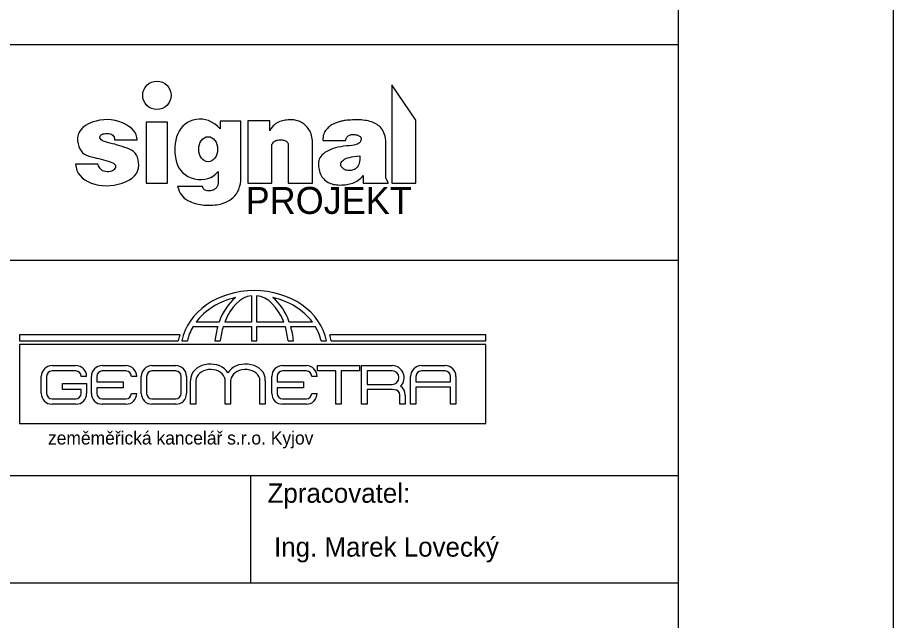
# Model space of a CAD drawing. Extents: x 2583 to 4283, y -3016 to -2572.
# Drawn here: x 3456.4 to 3537.7, y -2917.2 to -2861.3 of the extents above; entities that cross this region are included whole.
import ezdxf

# ---------------------------------------------------------------- set-up
doc = ezdxf.new("R2010")
doc.units = 0
for name, color, linetype in [('Default', 7, 'Continuous'), ('Vrstva 1', 7, 'Continuous'), ('Vrstva 11', 7, 'Continuous'), ('Vrstva 17', 7, 'Continuous'), ('Vrstva 6', 7, 'Continuous')]:
    doc.layers.add(name, color=color, linetype=linetype)

msp = doc.modelspace()

# ---------------------------------------------------------------- linework, layer by layer
at = {"layer": 'Default'}
msp.add_lwpolyline([(3327.684, -3015.765), (3537.684, -3015.765), (3537.684, -2718.765), (3327.684, -2718.765)], close=True, dxfattribs=at)
at = {"layer": 'Vrstva 1'}
msp.add_lwpolyline([(3347.684, -2738.765), (3517.684, -2738.765), (3517.684, -2998.765), (3347.684, -2998.765)], close=True, dxfattribs=at)
at = {"layer": 'Vrstva 11'}
for points in [[(3493.348, -2876.644), (3493.348, -2870.804), (3491.108, -2867.524), (3491.108, -2876.644), (3493.348, -2876.644)], [(3464.62, -2876.879), (3464.982, -2876.862), (3465.348, -2876.814), (3465.719, -2876.735), (3466.095, -2876.625), (3466.45, -2876.489), (3466.758, -2876.333), (3467.019, -2876.157), (3467.233, -2875.961), (3467.4, -2875.745), (3467.521, -2875.509), (3467.594, -2875.253), (3467.621, -2874.977), (3467.61, -2874.704), (3467.572, -2874.455), (3467.506, -2874.231), (3467.412, -2874.031), (3467.291, -2873.856), (3467.141, -2873.706), (3466.964, -2873.581), (3466.76, -2873.48), (3466.54, -2873.394), (3466.318, -2873.312), (3466.094, -2873.235), (3465.868, -2873.162), (3465.639, -2873.094), (3465.408, -2873.029), (3465.174, -2872.97), (3464.939, -2872.914), (3464.717, -2872.859), (3464.526, -2872.8), (3464.365, -2872.737), (3464.235, -2872.67), (3464.135, -2872.599), (3464.065, -2872.524), (3464.026, -2872.445), (3464.018, -2872.362), (3464.034, -2872.282), (3464.071, -2872.213), (3464.127, -2872.155), (3464.203, -2872.108), (3464.299, -2872.072), (3464.414, -2872.046), (3464.55, -2872.032), (3464.705, -2872.028), (3464.86, -2872.039), (3464.996, -2872.068), (3465.111, -2872.115), (3465.205, -2872.181), (3465.28, -2872.265), (3465.335, -2872.367), (3465.369, -2872.487), (3465.384, -2872.626), (3467.463, -2872.626), (3467.444, -2872.384), (3467.381, -2872.155), (3467.276, -2871.937), (3467.128, -2871.733), (3466.938, -2871.542), (3466.704, -2871.363), (3466.427, -2871.197), (3466.108, -2871.043), (3465.766, -2870.914), (3465.421, -2870.819), (3465.073, -2870.76), (3464.723, -2870.735), (3464.37, -2870.745), (3464.014, -2870.79), (3463.656, -2870.869), (3463.295, -2870.984), (3462.957, -2871.126), (3462.668, -2871.289), (3462.427, -2871.472), (3462.235, -2871.676), (3462.091, -2871.901), (3461.997, -2872.145), (3461.95, -2872.411), (3461.953, -2872.697), (3461.992, -2872.978), (3462.058, -2873.23), (3462.151, -2873.453), (3462.269, -2873.645), (3462.414, -2873.809), (3462.585, -2873.943), (3462.782, -2874.047), (3463.005, -2874.122), (3463.24, -2874.182), (3463.471, -2874.241), (3463.699, -2874.3), (3463.923, -2874.359), (3464.143, -2874.418), (3464.36, -2874.476), (3464.573, -2874.534), (3464.783, -2874.592), (3464.975, -2874.652), (3465.136, -2874.716), (3465.267, -2874.785), (3465.366, -2874.859), (3465.435, -2874.937), (3465.473, -2875.019), (3465.48, -2875.106), (3465.456, -2875.197), (3465.409, -2875.285), (3465.348, -2875.362), (3465.273, -2875.426), (3465.183, -2875.479), (3465.079, -2875.521), (3464.96, -2875.551), (3464.827, -2875.569), (3464.68, -2875.576), (3464.532, -2875.566), (3464.396, -2875.532), (3464.272, -2875.477), (3464.161, -2875.398), (3464.062, -2875.297), (3463.976, -2875.173), (3463.902, -2875.027), (3463.84, -2874.858), (3461.76, -2874.858), (3461.804, -2875.165), (3461.887, -2875.447), (3462.01, -2875.705), (3462.173, -2875.939), (3462.375, -2876.148), (3462.617, -2876.333), (3462.898, -2876.494), (3463.219, -2876.631), (3463.562, -2876.74), (3463.91, -2876.817), (3464.263, -2876.864), (3464.62, -2876.879)], [(3470.308, -2876.644), (3470.308, -2870.964), (3468.308, -2870.964), (3468.308, -2876.644), (3470.308, -2876.644)], [(3474.168, -2878.686), (3474.336, -2878.682), (3474.506, -2878.674), (3474.678, -2878.66), (3474.852, -2878.642), (3475.026, -2878.615), (3475.2, -2878.576), (3475.374, -2878.525), (3475.547, -2878.462), (3475.72, -2878.386), (3475.893, -2878.298), (3476.066, -2878.199), (3476.238, -2878.087), (3476.402, -2877.957), (3476.551, -2877.804), (3476.683, -2877.629), (3476.8, -2877.43), (3476.901, -2877.208), (3476.986, -2876.963), (3477.055, -2876.695), (3477.108, -2876.404), (3477.108, -2870.884), (3475.188, -2870.884), (3475.188, -2871.604), (3474.922, -2871.349), (3474.652, -2871.136), (3474.377, -2870.964), (3474.098, -2870.833), (3473.815, -2870.743), (3473.528, -2870.694), (3473.236, -2870.687), (3472.94, -2870.72), (3472.653, -2870.788), (3472.388, -2870.885), (3472.144, -2871.011), (3471.922, -2871.164), (3471.722, -2871.347), (3471.544, -2871.558), (3471.388, -2871.797), (3471.253, -2872.065), (3471.142, -2872.351), (3471.057, -2872.644), (3470.998, -2872.944), (3470.965, -2873.251), (3470.958, -2873.566), (3470.977, -2873.888), (3471.022, -2874.216), (3471.093, -2874.553), (3471.193, -2874.876), (3471.325, -2875.167), (3471.491, -2875.425), (3471.689, -2875.65), (3471.92, -2875.843), (3472.183, -2876.003), (3472.479, -2876.13), (3472.808, -2876.225), (3473.144, -2876.283), (3473.463, -2876.3), (3473.763, -2876.277), (3474.046, -2876.213), (3474.312, -2876.108), (3474.559, -2875.963), (3474.789, -2875.776), (3475, -2875.55), (3475, -2876.626), (3474.982, -2876.714), (3474.959, -2876.796), (3474.931, -2876.871), (3474.899, -2876.942), (3474.863, -2877.006), (3474.822, -2877.065), (3474.776, -2877.118), (3474.726, -2877.165), (3474.67, -2877.207), (3474.608, -2877.243), (3474.538, -2877.274), (3474.461, -2877.3), (3474.377, -2877.32), (3474.286, -2877.335), (3474.188, -2877.344), (3474.083, -2877.348), (3473.979, -2877.343), (3473.886, -2877.324), (3473.802, -2877.292), (3473.729, -2877.247), (3473.666, -2877.189), (3473.614, -2877.117), (3473.571, -2877.032), (3473.539, -2876.934), (3471.232, -2876.934), (3471.301, -2877.162), (3471.384, -2877.371), (3471.481, -2877.561), (3471.592, -2877.732), (3471.717, -2877.885), (3471.855, -2878.019), (3472.008, -2878.134), (3472.174, -2878.23), (3472.346, -2878.313), (3472.517, -2878.387), (3472.686, -2878.453), (3472.854, -2878.51), (3473.02, -2878.558), (3473.185, -2878.598), (3473.348, -2878.629), (3473.51, -2878.652), (3473.672, -2878.668), (3473.835, -2878.679), (3474.001, -2878.685), (3474.168, -2878.686)], [(3483.748, -2876.644), (3483.748, -2872.844), (3483.745, -2872.674), (3483.731, -2872.511), (3483.706, -2872.354), (3483.671, -2872.204), (3483.625, -2872.06), (3483.568, -2871.924), (3483.5, -2871.793), (3483.421, -2871.67), (3483.336, -2871.553), (3483.249, -2871.445), (3483.16, -2871.345), (3483.069, -2871.254), (3482.976, -2871.17), (3482.881, -2871.095), (3482.784, -2871.028), (3482.685, -2870.969), (3482.583, -2870.918), (3482.477, -2870.873), (3482.366, -2870.836), (3482.251, -2870.806), (3482.131, -2870.782), (3482.008, -2870.765), (3481.88, -2870.756), (3481.748, -2870.753), (3481.614, -2870.756), (3481.481, -2870.764), (3481.35, -2870.777), (3481.22, -2870.795), (3481.091, -2870.818), (3480.963, -2870.846), (3480.836, -2870.879), (3480.711, -2870.917), (3480.587, -2870.965), (3480.466, -2871.03), (3480.347, -2871.111), (3480.231, -2871.209), (3480.116, -2871.323), (3480.005, -2871.453), (3479.895, -2871.6), (3479.788, -2871.764), (3479.788, -2870.844), (3477.748, -2870.844), (3477.748, -2876.644), (3479.988, -2876.644), (3479.988, -2873.084), (3480.023, -2872.993), (3480.067, -2872.912), (3480.121, -2872.841), (3480.186, -2872.78), (3480.26, -2872.729), (3480.344, -2872.688), (3480.438, -2872.657), (3480.542, -2872.636), (3480.648, -2872.623), (3480.749, -2872.616), (3480.844, -2872.615), (3480.934, -2872.62), (3481.019, -2872.632), (3481.099, -2872.649), (3481.173, -2872.673), (3481.242, -2872.703), (3481.305, -2872.737), (3481.359, -2872.776), (3481.404, -2872.818), (3481.442, -2872.864), (3481.471, -2872.913), (3481.492, -2872.966), (3481.504, -2873.023), (3481.508, -2873.084), (3481.508, -2876.644), (3483.748, -2876.644)], [(3486.311, -2876.808), (3486.473, -2876.805), (3486.63, -2876.796), (3486.784, -2876.782), (3486.933, -2876.762), (3487.077, -2876.736), (3487.217, -2876.705), (3487.353, -2876.667), (3487.485, -2876.624), (3487.614, -2876.573), (3487.741, -2876.511), (3487.866, -2876.44), (3487.99, -2876.357), (3488.112, -2876.264), (3488.232, -2876.161), (3488.351, -2876.048), (3488.468, -2875.924), (3488.468, -2876.644), (3490.788, -2876.644), (3490.788, -2876.564), (3490.548, -2876.164), (3490.548, -2872.684), (3490.522, -2872.479), (3490.486, -2872.289), (3490.441, -2872.113), (3490.386, -2871.952), (3490.321, -2871.805), (3490.247, -2871.673), (3490.164, -2871.555), (3490.071, -2871.452), (3489.97, -2871.359), (3489.862, -2871.273), (3489.749, -2871.195), (3489.629, -2871.123), (3489.503, -2871.058), (3489.37, -2871), (3489.232, -2870.948), (3489.087, -2870.904), (3488.935, -2870.866), (3488.776, -2870.834), (3488.609, -2870.808), (3488.436, -2870.787), (3488.255, -2870.772), (3488.067, -2870.763), (3487.872, -2870.759), (3487.67, -2870.761), (3487.471, -2870.767), (3487.287, -2870.775), (3487.118, -2870.786), (3486.963, -2870.799), (3486.823, -2870.814), (3486.698, -2870.831), (3486.588, -2870.85), (3486.492, -2870.872), (3486.404, -2870.896), (3486.314, -2870.921), (3486.224, -2870.949), (3486.134, -2870.978), (3486.042, -2871.01), (3485.95, -2871.043), (3485.857, -2871.079), (3485.764, -2871.116), (3485.671, -2871.158), (3485.578, -2871.206), (3485.487, -2871.262), (3485.397, -2871.324), (3485.308, -2871.393), (3485.22, -2871.469), (3485.132, -2871.551), (3485.046, -2871.641), (3484.966, -2871.738), (3484.897, -2871.845), (3484.838, -2871.962), (3484.791, -2872.087), (3484.754, -2872.222), (3484.728, -2872.367), (3484.713, -2872.521), (3484.708, -2872.684), (3486.828, -2872.684), (3486.844, -2872.587), (3486.868, -2872.5), (3486.901, -2872.422), (3486.942, -2872.353), (3486.992, -2872.294), (3487.051, -2872.243), (3487.118, -2872.202), (3487.194, -2872.169), (3487.275, -2872.145), (3487.356, -2872.127), (3487.437, -2872.116), (3487.519, -2872.111), (3487.602, -2872.113), (3487.685, -2872.121), (3487.769, -2872.136), (3487.853, -2872.157), (3487.933, -2872.183), (3488.005, -2872.211), (3488.067, -2872.24), (3488.121, -2872.272), (3488.166, -2872.307), (3488.203, -2872.343), (3488.23, -2872.381), (3488.249, -2872.422), (3488.26, -2872.465), (3488.265, -2872.511), (3488.264, -2872.559), (3488.257, -2872.611), (3488.243, -2872.665), (3488.223, -2872.722), (3488.197, -2872.782), (3488.165, -2872.844), (3488.114, -2872.905), (3488.033, -2872.961), (3487.921, -2873.012), (3487.78, -2873.057), (3487.608, -2873.097), (3487.405, -2873.132), (3487.173, -2873.162), (3486.91, -2873.186), (3486.638, -2873.212), (3486.378, -2873.25), (3486.131, -2873.298), (3485.896, -2873.356), (3485.673, -2873.425), (3485.463, -2873.505), (3485.265, -2873.595), (3485.079, -2873.695), (3484.91, -2873.804), (3484.761, -2873.916), (3484.634, -2874.033), (3484.527, -2874.155), (3484.442, -2874.281), (3484.377, -2874.412), (3484.333, -2874.547), (3484.31, -2874.687), (3484.302, -2874.828), (3484.303, -2874.968), (3484.313, -2875.107), (3484.332, -2875.245), (3484.36, -2875.382), (3484.397, -2875.517), (3484.443, -2875.652), (3484.498, -2875.785), (3484.561, -2875.913), (3484.631, -2876.032), (3484.708, -2876.143), (3484.791, -2876.244), (3484.882, -2876.337), (3484.98, -2876.421), (3485.084, -2876.495), (3485.196, -2876.562), (3485.314, -2876.619), (3485.438, -2876.669), (3485.568, -2876.712), (3485.704, -2876.746), (3485.847, -2876.773), (3485.995, -2876.792), (3486.15, -2876.804), (3486.311, -2876.808)], [(3487.027, -2875.463), (3486.924, -2875.443), (3486.829, -2875.415), (3486.742, -2875.379), (3486.663, -2875.335), (3486.593, -2875.284), (3486.53, -2875.225), (3486.475, -2875.158), (3486.428, -2875.083), (3486.394, -2875.006), (3486.376, -2874.929), (3486.375, -2874.853), (3486.39, -2874.778), (3486.423, -2874.703), (3486.472, -2874.63), (3486.538, -2874.558), (3486.62, -2874.486), (3486.724, -2874.418), (3486.852, -2874.355), (3487.006, -2874.297), (3487.185, -2874.245), (3487.389, -2874.198), (3487.619, -2874.156), (3487.873, -2874.119), (3488.153, -2874.088), (3488.157, -2874.287), (3488.149, -2874.469), (3488.127, -2874.635), (3488.092, -2874.784), (3488.045, -2874.918), (3487.984, -2875.035), (3487.911, -2875.137), (3487.825, -2875.222), (3487.731, -2875.293), (3487.636, -2875.353), (3487.539, -2875.4), (3487.44, -2875.436), (3487.339, -2875.461), (3487.237, -2875.473), (3487.133, -2875.474), (3487.027, -2875.463)]]:
    msp.add_lwpolyline(points, dxfattribs=at)
msp.add_circle((3469.308, -2868.484), 1.32, dxfattribs=at)
msp.add_ellipse((3474.068, -2873.484), major_axis=(0, 1.16), ratio=0.758621, dxfattribs=at)
at = {"layer": 'Vrstva 17'}
for p, q in [((3478.079, -2887.077), (3478.079, -2889.523)), ((3478.586, -2889.523), (3478.586, -2887.075)), ((3475.085, -2889.523), (3472.94, -2889.523)), ((3478.079, -2889.523), (3475.602, -2889.523)), ((3481.08, -2889.523), (3478.586, -2889.523)), ((3483.742, -2889.523), (3481.597, -2889.523)), ((3472.665, -2889.935), (3474.953, -2889.935)), ((3475.463, -2889.935), (3478.079, -2889.935)), ((3478.079, -2889.935), (3478.079, -2891.255)), ((3478.586, -2891.255), (3478.586, -2889.935)), ((3478.586, -2889.935), (3481.22, -2889.935)), ((3481.73, -2889.935), (3484.017, -2889.935)), ((3471.434, -2890.724), (3456.554, -2890.724)), ((3456.554, -2890.724), (3456.554, -2891.255)), ((3456.554, -2891.255), (3471.297, -2891.255)), ((3471.622, -2891.255), (3472.139, -2891.255)), ((3474.696, -2891.255), (3475.196, -2891.255)), ((3478.079, -2891.255), (3478.586, -2891.255)), ((3481.487, -2891.255), (3481.987, -2891.255)), ((3484.543, -2891.255), (3485.06, -2891.255)), ((3499.832, -2890.724), (3485.354, -2890.724)), ((3485.492, -2891.255), (3499.832, -2891.255)), ((3499.832, -2891.255), (3499.832, -2890.724)), ((3499.831, -2891.599), (3456.548, -2891.599)), ((3456.548, -2891.599), (3456.548, -2898.937)), ((3499.831, -2898.937), (3499.831, -2891.599)), ((3459.573, -2893.565), (3461.783, -2893.565)), ((3464.229, -2893.565), (3466.44, -2893.565)), ((3468.853, -2893.565), (3471.063, -2893.565)), ((3480.971, -2893.565), (3483.182, -2893.565)), ((3488.309, -2893.565), (3491.153, -2893.565)), ((3493.857, -2893.565), (3496.068, -2893.565)), ((3458.575, -2896.149), (3458.575, -2894.563)), ((3459.074, -2894.563), (3459.074, -2896.149)), ((3461.783, -2894.064), (3459.573, -2894.064)), ((3462.781, -2894.563), (3462.282, -2894.563)), ((3463.231, -2896.149), (3463.231, -2894.563)), ((3463.73, -2894.563), (3463.73, -2895.074)), ((3466.44, -2894.064), (3464.229, -2894.064)), ((3467.437, -2894.563), (3466.939, -2894.563)), ((3467.855, -2896.149), (3467.855, -2894.563)), ((3468.354, -2894.563), (3468.354, -2896.149)), ((3471.063, -2894.064), (3468.853, -2894.064)), ((3471.563, -2896.149), (3471.563, -2894.563)), ((3472.061, -2894.563), (3472.061, -2896.149)), ((3479.974, -2896.149), (3479.974, -2894.563)), ((3480.472, -2894.563), (3480.472, -2895.074)), ((3483.182, -2894.064), (3480.971, -2894.064)), ((3484.18, -2894.563), (3483.681, -2894.563)), ((3485.914, -2897.147), (3485.914, -2894.052)), ((3486.418, -2894.052), (3486.418, -2897.147)), ((3491.153, -2894.054), (3488.813, -2894.054)), ((3488.813, -2894.054), (3488.813, -2895.304)), ((3492.859, -2897.147), (3492.859, -2894.563)), ((3493.358, -2894.563), (3493.358, -2895.072)), ((3496.068, -2894.064), (3493.857, -2894.064)), ((3496.567, -2895.072), (3496.567, -2894.563)), ((3497.065, -2894.563), (3497.065, -2897.147)), ((3460.548, -2895.771), (3460.548, -2895.227)), ((3460.548, -2895.227), (3462.781, -2895.227)), ((3462.781, -2895.227), (3462.781, -2896.149)), ((3463.73, -2895.074), (3466.173, -2895.074)), ((3466.173, -2895.074), (3466.173, -2895.618)), ((3472.434, -2897.147), (3472.434, -2894.962)), ((3472.934, -2894.962), (3472.934, -2897.147)), ((3475.654, -2897.147), (3475.654, -2894.962)), ((3476.154, -2894.962), (3476.154, -2897.147)), ((3478.873, -2897.147), (3478.873, -2894.962)), ((3479.373, -2894.962), (3479.373, -2897.147)), ((3480.472, -2895.074), (3482.915, -2895.074)), ((3482.915, -2895.074), (3482.915, -2895.618)), ((3488.813, -2895.304), (3491.153, -2895.304)), ((3493.358, -2895.072), (3496.567, -2895.072)), ((3462.282, -2895.771), (3460.548, -2895.771)), ((3462.282, -2896.149), (3462.282, -2895.771)), ((3466.173, -2895.618), (3463.73, -2895.618)), ((3463.73, -2895.618), (3463.73, -2896.149)), ((3466.939, -2896.149), (3467.437, -2896.149)), ((3482.915, -2895.618), (3480.472, -2895.618)), ((3480.472, -2895.618), (3480.472, -2896.149)), ((3483.681, -2896.149), (3484.18, -2896.149)), ((3491.153, -2895.793), (3488.813, -2895.793)), ((3491.367, -2895.797), (3491.153, -2895.793)), ((3491.866, -2897.147), (3491.866, -2896.296)), ((3492.365, -2896.296), (3492.365, -2897.147)), ((3496.567, -2895.575), (3493.358, -2895.575)), ((3493.358, -2895.575), (3493.358, -2897.147)), ((3496.567, -2897.147), (3496.567, -2895.575)), ((3459.573, -2896.648), (3461.783, -2896.648)), ((3461.783, -2897.147), (3459.573, -2897.147)), ((3464.229, -2896.648), (3466.44, -2896.648)), ((3466.44, -2897.147), (3464.229, -2897.147)), ((3468.853, -2896.648), (3471.063, -2896.648)), ((3471.063, -2897.147), (3468.853, -2897.147)), ((3472.934, -2897.147), (3472.434, -2897.147)), ((3476.154, -2897.147), (3475.654, -2897.147)), ((3479.373, -2897.147), (3478.873, -2897.147)), ((3480.971, -2896.648), (3483.182, -2896.648)), ((3483.182, -2897.147), (3480.971, -2897.147)), ((3486.418, -2897.147), (3485.914, -2897.147)), ((3492.365, -2897.147), (3491.866, -2897.147)), ((3493.358, -2897.147), (3492.859, -2897.147)), ((3497.065, -2897.147), (3496.567, -2897.147)), ((3456.548, -2898.937), (3499.831, -2898.937))]:
    msp.add_line(p, q, dxfattribs=at)
for points in [[(3485.914, -2894.052), (3484.216, -2894.052), (3484.216, -2893.565), (3488.13, -2893.565)], [(3488.13, -2893.565), (3488.13, -2894.052), (3486.418, -2894.052)], [(3488.813, -2895.793), (3488.813, -2897.147), (3488.309, -2897.147), (3488.309, -2893.565)]]:
    msp.add_lwpolyline(points, dxfattribs=at)
for centre, radius, start, end in [((3459.573, -2894.563), 0.998, 90, 180), ((3461.783, -2894.563), 0.998, 360, 90), ((3464.229, -2894.563), 0.998, 90, 180), ((3466.44, -2894.563), 0.998, 360, 90), ((3468.853, -2894.563), 0.998, 90, 180), ((3471.063, -2894.563), 0.998, 360, 90), ((3480.971, -2894.563), 0.998, 90, 180), ((3483.182, -2894.563), 0.998, 360, 90), ((3491.153, -2894.679), 1.114, 314.45734, 90), ((3493.857, -2894.563), 0.998, 90, 180), ((3496.068, -2894.563), 0.998, 360, 90), ((3459.573, -2894.563), 0.499, 90, 180), ((3461.783, -2894.563), 0.499, 0, 90), ((3464.229, -2894.563), 0.499, 90, 180), ((3466.44, -2894.563), 0.499, 0, 90), ((3468.853, -2894.563), 0.499, 90, 180), ((3471.063, -2894.563), 0.499, 0, 90), ((3474.371, -2895.012), 1.938, 166.96576, 178.52091), ((3474.699, -2895.027), 0.957, 3.86486, 22.41569), ((3477.387, -2895.084), 1.238, 162.61388, 174.3506), ((3477.436, -2895.012), 1.938, 1.47909, 13.03424), ((3480.971, -2894.563), 0.499, 90, 180), ((3483.182, -2894.563), 0.499, 0, 90), ((3491.153, -2894.679), 0.625, 270, 90), ((3493.857, -2894.563), 0.499, 90, 180), ((3496.068, -2894.563), 0.499, 0, 90), ((3491.367, -2896.296), 0.998, 360, 55.44734), ((3459.573, -2896.149), 0.998, 180, 270), ((3459.573, -2896.149), 0.499, 180, 270), ((3461.783, -2896.149), 0.998, 270, 0), ((3461.783, -2896.149), 0.499, 270, 0), ((3464.229, -2896.149), 0.998, 180, 270), ((3464.229, -2896.149), 0.499, 180, 270), ((3466.44, -2896.149), 0.998, 270, 0), ((3466.44, -2896.149), 0.499, 270, 0), ((3468.853, -2896.149), 0.998, 180, 270), ((3468.853, -2896.149), 0.499, 180, 270), ((3471.063, -2896.149), 0.998, 270, 0), ((3471.063, -2896.149), 0.499, 270, 0), ((3480.971, -2896.149), 0.998, 180, 270), ((3480.971, -2896.149), 0.499, 180, 270), ((3483.182, -2896.149), 0.998, 270, 0), ((3483.182, -2896.149), 0.499, 270, 0), ((3491.367, -2896.296), 0.499, 0, 90)]:
    msp.add_arc(centre, radius, start, end, dxfattribs=at)
for centre, major_axis, ratio, start_param, end_param in [((3478.341, -2892.127), (-6.804, 0), 0.811768, 3.300239, 6.124539), ((3478.341, -2892.127), (-6.296, 0), 0.804826, 4.992897, 5.743383), ((3478.341, -2892.127), (0, 5.524), 0.668443, 0.491666, 1.079789), ((3478.341, -2892.127), (0, 5.067), 0.630136, 0.08224, 1.030995), ((3478.341, -2892.127), (0, 5.067), 0.630136, 5.252191, 6.206521), ((3478.341, -2892.127), (0, 5.524), 0.668443, 5.203397, 5.79152), ((3478.341, -2892.127), (-6.296, 0), 0.804826, 3.681394, 4.431881), ((3478.341, -2892.127), (-6.296, 0), 0.804826, 5.835664, 6.110118), ((3478.341, -2892.127), (0, 5.524), 0.668443, 1.16256, 1.41215), ((3478.341, -2892.127), (0, 5.067), 0.630136, 1.123275, 1.397729), ((3478.341, -2892.127), (0, 5.067), 0.630136, 4.885456, 5.159911), ((3478.341, -2892.127), (0, 5.524), 0.668443, 4.871035, 5.120625), ((3478.341, -2892.127), (-6.296, 0), 0.804826, 3.31466, 3.589114), ((3478.015, -2892.127), (-6.804, 0), 0.811768, 6.026233, 6.124539), ((3478.773, -2892.127), (-6.804, 0), 0.811768, 3.300239, 3.398545), ((3474.263, -2894.807), (1.805, 0), 0.766187, 0.429647, 2.97338), ((3474.288, -2894.962), (1.354, 0), 0.766187, 0.29376, 3.141593), ((3477.544, -2894.807), (-1.805, 0), 0.766187, 3.309805, 5.853538), ((3477.519, -2894.962), (-1.354, 0), 0.766187, 3.141593, 6.041607)]:
    msp.add_ellipse(centre, major_axis=major_axis, ratio=ratio, start_param=start_param, end_param=end_param, dxfattribs=at)
at = {"layer": 'Vrstva 6'}
for p, q in [((3347.684, -2883.765), (3517.684, -2883.765)), ((3347.684, -2903.765), (3517.684, -2903.765)), ((3478.034, -2913.765), (3478.034, -2903.765))]:
    msp.add_line(p, q, dxfattribs=at)
msp.add_lwpolyline([(3347.684, -2863.765), (3517.684, -2863.765), (3517.684, -2913.765), (3347.684, -2913.765)], close=True, dxfattribs=at)

# ---------------------------------------------------------------- texts
at = {"layer": 'Vrstva 11'}
msp.add_text('PROJEKT', height=2.5, dxfattribs=at).set_placement((3477.549, -2879.487))
at = {"layer": 'Vrstva 17'}
msp.add_text('zeměměřická kancelář s.r.o. Kyjov', height=1.20984, dxfattribs=at).set_placement((3459.199, -2900.886))
at = {"layer": 'Vrstva 6'}
for s, p in [('Zpracovatel:', (3479.58, -2906.291)), ('Ing. Marek Lovecký', (3480.181, -2911.291))]:
    msp.add_text(s, height=1.8, dxfattribs=at).set_placement(p)

doc.saveas('drawing.dxf')
